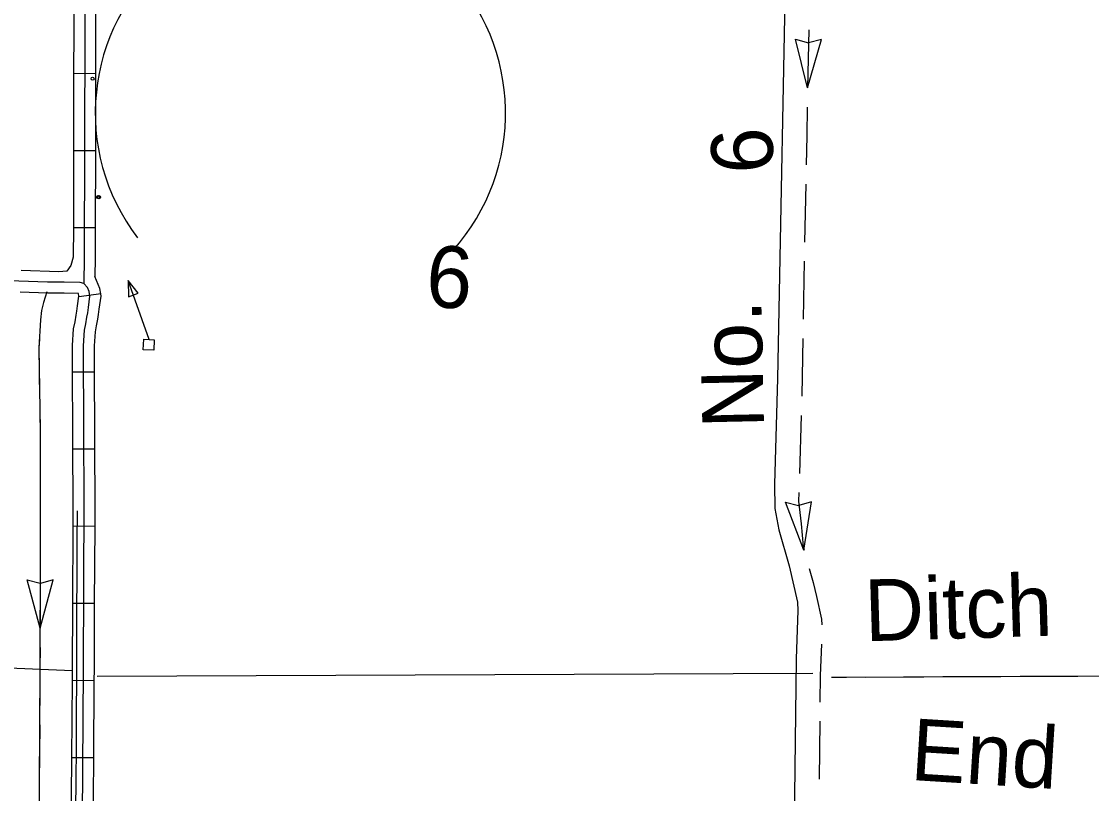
# Model space of a CAD drawing. Extents: x 1366406 to 1373462, y 376856 to 381998.
# Drawn here: x 1369434.3 to 1369553, y 380013.3 to 380098.9 of the extents above; entities that cross this region are included whole.
import ezdxf

# ---------------------------------------------------------------- set-up
doc = ezdxf.new("R2010")
doc.units = 0
for name, color, linetype in [('32', 7, 'Continuous'), ('33', 7, 'Continuous'), ('41', 7, 'Continuous'), ('43', 7, 'Continuous'), ('5', 7, 'Continuous'), ('56', 7, 'Continuous'), ('6', 7, 'Continuous'), ('63', 7, 'Continuous')]:
    doc.layers.add(name, color=color, linetype=linetype)

msp = doc.modelspace()

# ---------------------------------------------------------------- linework, layer by layer
at = {"layer": '32'}
for p, q in [((1369440.08, 380093.13), (1369442.51, 380093.12)), ((1369440.06, 380084.57), (1369442.49, 380084.57)), ((1369440.05, 380076.02), (1369442.48, 380076.02)), ((1369443.08, 380068.67), (1369440.68, 380068.33)), ((1369442.4, 380060), (1369439.97, 380060)), ((1369442.43, 380051.45), (1369440, 380051.44)), ((1369442.45, 380042.89), (1369440.02, 380042.9)), ((1369442.41, 380034.33), (1369439.98, 380034.35)), ((1369442.37, 380025.78), (1369439.94, 380025.79)), ((1369442.31, 380017.22), (1369439.88, 380017.24))]:
    msp.add_line(p, q, dxfattribs=at)
for points in [[(1369443.17, 380281.29), (1369442.94, 380259.58), (1369442.76, 380233.54), (1369442.42, 380199.08), (1369441.85, 380156.3), (1369441.78, 380148.99), (1369441.3, 380113.39), (1369441.31, 380097.83), (1369441.25, 380072.65), (1369441.2, 380069.82)], [(1369440.09, 380101.68), (1369440.09, 380097.83), (1369440.08, 380093.13)], [(1369442.52, 380101.68), (1369442.52, 380097.82), (1369442.51, 380093.12)], [(1369440.08, 380093.13), (1369440.06, 380084.57)], [(1369442.51, 380093.12), (1369442.49, 380084.57)], [(1369440.06, 380084.57), (1369440.05, 380076.02)], [(1369442.49, 380084.57), (1369442.48, 380076.02)], [(1369440.05, 380076.02), (1369440.04, 380072.75)], [(1369442.48, 380076.02), (1369442.47, 380072.64), (1369442.43, 380070.6)], [(1369440.04, 380072.75), (1369439.78, 380071.82), (1369439.31, 380071.17), (1369438.43, 380071.12)], [(1369440.86, 379983.02), (1369441.17, 380027.05), (1369441.25, 380045.71), (1369441.2, 380053.42), (1369441.18, 380062.92), (1369441.28, 380064.63), (1369441.42, 380065.33), (1369441.56, 380066.09), (1369441.64, 380066.56), (1369441.72, 380067.16), (1369441.89, 380068.43), (1369441.81, 380068.95), (1369441.63, 380069.39), (1369441.2, 380069.82), (1369440.8, 380069.93), (1369439.02, 380069.97), (1369437.18, 380069.95), (1369419.08, 380070.61), (1369411.46, 380070.91), (1369406.38, 380071.21), (1369403.18, 380071.34), (1369398.26, 380071.64), (1369392.89, 380071.86)], [(1369438.43, 380071.12), (1369434.25, 380071.27)], [(1369443.08, 380068.67), (1369443, 380069.28), (1369442.43, 380070.6)], [(1369440.68, 380068.33), (1369440.63, 380068.62), (1369440.6, 380068.7), (1369440.58, 380068.72), (1369439.01, 380068.75), (1369437.16, 380068.73), (1369434.16, 380068.84)], [(1369442.4, 380060), (1369442.39, 380062.89), (1369442.49, 380064.47), (1369442.61, 380065.11), (1369442.76, 380065.88), (1369442.84, 380066.39), (1369442.92, 380066.99), (1369443.12, 380068.43), (1369443.08, 380068.67)], [(1369439.97, 380060), (1369439.96, 380062.96), (1369440.08, 380064.78), (1369440.23, 380065.56), (1369440.36, 380066.29), (1369440.43, 380066.74), (1369440.51, 380067.33), (1369440.66, 380068.42), (1369440.68, 380068.33)], [(1369440, 380051.44), (1369439.99, 380053.42), (1369439.97, 380060)], [(1369442.43, 380051.45), (1369442.42, 380053.43), (1369442.4, 380060)], [(1369440.02, 380042.9), (1369440.04, 380045.71), (1369440, 380051.44)], [(1369442.45, 380042.89), (1369442.47, 380045.71), (1369442.43, 380051.45)], [(1369439.98, 380034.35), (1369440.02, 380042.9)], [(1369442.41, 380034.33), (1369442.45, 380042.89)], [(1369439.94, 380025.79), (1369439.95, 380027.06), (1369439.98, 380034.35)], [(1369442.37, 380025.78), (1369442.38, 380027.04), (1369442.41, 380034.33)], [(1369439.88, 380017.24), (1369439.94, 380025.79)], [(1369442.31, 380017.22), (1369442.37, 380025.78)], [(1369439.82, 380008.69), (1369439.88, 380017.24)], [(1369442.25, 380008.67), (1369442.31, 380017.22)]]:
    msp.add_lwpolyline(points, dxfattribs=at)
at = {"layer": '33'}
msp.add_lwpolyline([(1369440.47, 380044.63), (1369440.42, 380041.14), (1369440.37, 380018.41), (1369440.31, 380014.64), (1369440.05, 379992.98), (1369439.98, 379985.97)], dxfattribs=at)
at = {"layer": '43'}
for p, q in [((1369521.51, 380091.52), (1369520.18, 380096.92)), ((1369520.18, 380096.92), (1369521.6, 380096.51)), ((1369521.51, 380091.52), (1369523.06, 380096.86)), ((1369523.06, 380096.86), (1369521.62, 380096.51)), ((1369519.06, 380045.56), (1369520.5, 380045.2)), ((1369521.08, 380040.26), (1369519.06, 380045.56)), ((1369521.94, 380045.6), (1369520.52, 380045.2)), ((1369521.08, 380040.26), (1369521.94, 380045.6)), ((1369434.94, 380036.96), (1369436.37, 380036.58)), ((1369436.35, 380031.59), (1369434.94, 380036.96)), ((1369436.35, 380031.59), (1369437.82, 380036.95)), ((1369437.82, 380036.95), (1369436.39, 380036.57))]:
    msp.add_line(p, q, dxfattribs=at)
for points in [[(1369519.17, 380110.84), (1369518.17, 380059.27), (1369517.82, 380047.57), (1369517.86, 380044.87), (1369518.32, 380042.52), (1369519.45, 380038.53), (1369520.37, 380034.48), (1369520.43, 380033.57), (1369520.22, 380028.22), (1369520.02, 380009.99)], [(1369521.64, 380097.93), (1369521.51, 380091.52)], [(1369521.47, 380089.38), (1369521.41, 380086.18)], [(1369521.41, 380086.18), (1369521.35, 380082.97)], [(1369521.31, 380080.83), (1369521.18, 380074.42)], [(1369521.14, 380072.28), (1369521.02, 380065.86)], [(1369437.12, 380068.91), (1369436.72, 380067.71), (1369436.53, 380066.84), (1369436.4, 380065.79), (1369436.22, 380062.69), (1369436.35, 380053.64), (1369436.36, 380040.16), (1369436.34, 380027.08), (1369435.67, 379910.63), (1369435.48, 379901.35)], [(1369437.12, 380068.91), (1369436.72, 380067.71), (1369436.53, 380066.84), (1369436.4, 380065.79)], [(1369436.28, 380063.66), (1369436.22, 380062.69), (1369436.3, 380057.25)], [(1369520.98, 380063.73), (1369520.85, 380057.4), (1369520.85, 380057.31)], [(1369436.33, 380055.11), (1369436.35, 380053.64), (1369436.35, 380048.69)], [(1369520.79, 380055.17), (1369520.59, 380048.76)], [(1369436.35, 380046.55), (1369436.36, 380040.16), (1369436.36, 380040.14)], [(1369520.53, 380046.63), (1369520.5, 380045.7), (1369520.79, 380043.18), (1369521.01, 380040.66), (1369521.11, 380040.27)], [(1369436.36, 380038), (1369436.35, 380031.59)], [(1369521.69, 380038.21), (1369522.13, 380036.66), (1369522.48, 380035.11)], [(1369522.48, 380035.11), (1369523.05, 380032.61), (1369523.09, 380031.96)], [(1369436.35, 380029.45), (1369436.34, 380027.08), (1369436.32, 380023.03)], [(1369523.04, 380029.83), (1369522.91, 380026.35), (1369522.88, 380023.41)], [(1369659.48, 380026.54), (1369652.36, 380026.39), (1369564.12, 380026.31), (1369524.16, 380026.13)], [(1369525.83, 380026.14), (1369524.16, 380026.13)], [(1369534.39, 380026.18), (1369527.97, 380026.15)], [(1369542.94, 380026.22), (1369536.52, 380026.19)], [(1369551.49, 380026.25), (1369545.08, 380026.23)], [(1369522.85, 380021.28), (1369522.78, 380014.86)], [(1369436.31, 380020.89), (1369436.29, 380017.69)], [(1369436.29, 380017.69), (1369436.27, 380014.48)]]:
    msp.add_lwpolyline(points, dxfattribs=at)
at = {"layer": '5'}
msp.add_lwpolyline([(1369522.08, 380026.56), (1369442.68, 380026.23)], dxfattribs=at)
at = {"layer": '56'}
msp.add_lwpolyline([(1369448.45, 380063.62), (1369446.12, 380070.16)], dxfattribs=at)
for points in [[(1369446.16, 380068.34), (1369447.24, 380068.73), (1369446.12, 380070.16)], [(1369447.79, 380062.48), (1369447.86, 380063.65), (1369449.03, 380063.58), (1369448.96, 380062.41)]]:
    msp.add_lwpolyline(points, close=True, dxfattribs=at)
for centre in [(1369442.18, 380092.53), (1369442.78, 380079.4), (1369442.89, 380079.39)]:
    msp.add_circle(centre, 0.169, dxfattribs=at)
at = {"layer": '6'}
msp.add_lwpolyline([(1369344.36, 380030.58), (1369355.75, 380030.44), (1369381.57, 380029.35), (1369439.95, 380026.9)], dxfattribs=at)
at = {"layer": '63'}
msp.add_arc((1369465.24, 380088.72), 22.76, 317.9431, 217.3999, dxfattribs=at)

# ---------------------------------------------------------------- texts
at = {"layer": '41'}
msp.add_text('End', height=6.843, rotation=356.4139, dxfattribs=at).set_placement((1369532.83, 380014.78))
at = {"layer": '43'}
for s, height, rotation, p in [('6', 6.84, 91.8691, (1369517.74, 380082.12)), ('No.', 6.843, 91.2544, (1369516.68, 380053.82)), ('Ditch', 6.843, 1.745, (1369527.91, 380030.14))]:
    msp.add_text(s, height=height, rotation=rotation, dxfattribs=at).set_placement(p)
at = {"layer": '5'}
msp.add_text('6', height=6.84, rotation=356.4139, dxfattribs=at).set_placement((1369479.03, 380067.28))

doc.saveas('drawing.dxf')
